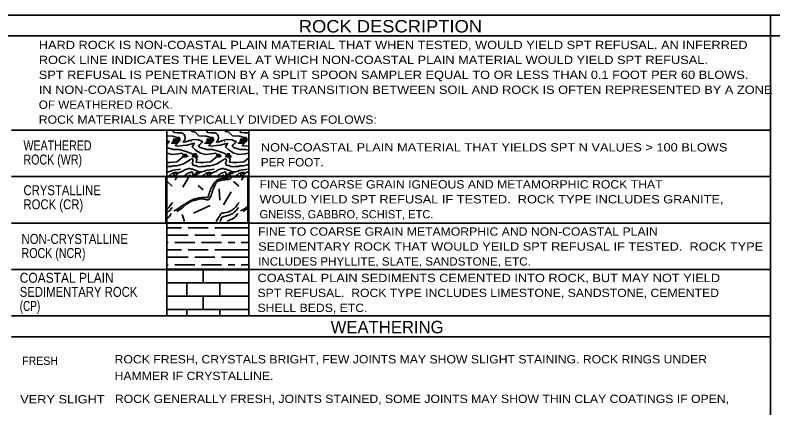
# Model space of a CAD drawing. Extents: x 2137492.6 to 2137529.1, y 2137475.8 to 2137563.
# Drawn here: x 2137510.82 to 2137519.94, y 2137553.49 to 2137558.22 of the extents above; entities that cross this region are included whole.
import ezdxf
from ezdxf.enums import TextEntityAlignment as Align

# ---------------------------------------------------------------- set-up
doc = ezdxf.new("R2010")
doc.units = 0
doc.header["$LTSCALE"] = 0.04
doc.layers.add('1', color=7, linetype='Continuous', lineweight=35)
doc.layers.add('2', color=7, linetype='Continuous')

msp = doc.modelspace()

# ---------------------------------------------------------------- linework, layer by layer
at = {"layer": '1'}
for p, q in [((2137493.171, 2137558.218), (2137528.371, 2137558.218)), ((2137519.912, 2137558.218), (2137519.912, 2137539.727)), ((2137493.171, 2137557.968), (2137528.371, 2137557.968)), ((2137519.912, 2137556.833), (2137510.771, 2137556.833)), ((2137512.642, 2137556.833), (2137512.642, 2137554.593)), ((2137512.642, 2137556.764), (2137512.708, 2137556.76)), ((2137513.63, 2137556.833), (2137513.63, 2137554.593)), ((2137512.693, 2137556.677), (2137512.772, 2137556.677)), ((2137512.709, 2137556.689), (2137512.779, 2137556.689)), ((2137512.716, 2137556.712), (2137512.797, 2137556.712)), ((2137512.797, 2137556.7), (2137512.716, 2137556.7)), ((2137512.798, 2137556.724), (2137512.719, 2137556.724)), ((2137512.884, 2137556.653), (2137512.929, 2137556.663)), ((2137513.096, 2137556.677), (2137513.174, 2137556.677)), ((2137513.111, 2137556.689), (2137513.182, 2137556.689)), ((2137513.119, 2137556.712), (2137513.2, 2137556.712)), ((2137513.2, 2137556.7), (2137513.119, 2137556.7)), ((2137513.2, 2137556.724), (2137513.122, 2137556.724)), ((2137513.287, 2137556.653), (2137513.331, 2137556.663)), ((2137513.498, 2137556.677), (2137513.576, 2137556.677)), ((2137513.514, 2137556.689), (2137513.584, 2137556.689)), ((2137513.521, 2137556.712), (2137513.602, 2137556.712)), ((2137513.602, 2137556.7), (2137513.521, 2137556.7)), ((2137513.603, 2137556.724), (2137513.524, 2137556.724)), ((2137512.884, 2137556.509), (2137512.835, 2137556.509)), ((2137512.841, 2137556.52), (2137512.9, 2137556.52)), ((2137512.88, 2137556.538), (2137512.847, 2137556.538)), ((2137512.888, 2137556.529), (2137512.848, 2137556.529)), ((2137512.927, 2137556.554), (2137512.906, 2137556.561)), ((2137512.951, 2137556.511), (2137513.02, 2137556.511)), ((2137513.003, 2137556.529), (2137512.963, 2137556.529)), ((2137512.963, 2137556.521), (2137513.013, 2137556.521)), ((2137512.964, 2137556.538), (2137512.998, 2137556.537)), ((2137512.965, 2137556.548), (2137512.999, 2137556.548)), ((2137513.287, 2137556.509), (2137513.238, 2137556.509)), ((2137513.244, 2137556.52), (2137513.302, 2137556.52)), ((2137513.283, 2137556.538), (2137513.249, 2137556.538)), ((2137513.291, 2137556.529), (2137513.25, 2137556.529)), ((2137513.33, 2137556.554), (2137513.308, 2137556.561)), ((2137513.353, 2137556.511), (2137513.423, 2137556.511)), ((2137513.405, 2137556.529), (2137513.365, 2137556.529)), ((2137513.365, 2137556.521), (2137513.416, 2137556.521)), ((2137513.367, 2137556.538), (2137513.4, 2137556.537)), ((2137513.368, 2137556.548), (2137513.401, 2137556.548)), ((2137513.629, 2137556.556), (2137513.63, 2137556.555)), ((2137512.642, 2137556.317), (2137512.643, 2137556.317)), ((2137512.74, 2137556.321), (2137512.772, 2137556.321)), ((2137512.74, 2137556.317), (2137512.768, 2137556.317)), ((2137512.74, 2137556.312), (2137512.764, 2137556.312)), ((2137512.74, 2137556.312), (2137512.76, 2137556.312)), ((2137512.951, 2137556.307), (2137512.954, 2137556.282)), ((2137513.011, 2137556.299), (2137512.964, 2137556.299)), ((2137512.979, 2137556.308), (2137513.033, 2137556.308)), ((2137512.991, 2137556.317), (2137513.046, 2137556.317)), ((2137513.143, 2137556.321), (2137513.175, 2137556.321)), ((2137513.143, 2137556.317), (2137513.171, 2137556.317)), ((2137513.143, 2137556.312), (2137513.167, 2137556.312)), ((2137513.143, 2137556.312), (2137513.163, 2137556.312)), ((2137513.354, 2137556.307), (2137513.357, 2137556.282)), ((2137513.413, 2137556.299), (2137513.367, 2137556.299)), ((2137513.381, 2137556.308), (2137513.435, 2137556.308)), ((2137513.393, 2137556.317), (2137513.448, 2137556.317)), ((2137513.545, 2137556.321), (2137513.577, 2137556.321)), ((2137513.545, 2137556.317), (2137513.573, 2137556.317)), ((2137513.545, 2137556.312), (2137513.569, 2137556.312)), ((2137513.545, 2137556.312), (2137513.565, 2137556.312)), ((2137519.912, 2137556.273), (2137510.771, 2137556.273)), ((2137512.646, 2137556.212), (2137512.709, 2137556.158)), ((2137512.765, 2137556.268), (2137512.742, 2137556.231)), ((2137512.908, 2137556.268), (2137512.836, 2137556.144)), ((2137513.446, 2137556.212), (2137513.509, 2137556.158)), ((2137513.565, 2137556.268), (2137513.542, 2137556.231)), ((2137513.02, 2137556.167), (2137513.082, 2137556.113)), ((2137513.272, 2137556.123), (2137513.281, 2137555.99)), ((2137513.416, 2137556.088), (2137513.325, 2137555.933)), ((2137512.963, 2137555.832), (2137513.166, 2137555.926)), ((2137513.618, 2137555.89), (2137513.562, 2137555.852)), ((2137512.827, 2137555.815), (2137512.854, 2137555.73)), ((2137519.912, 2137555.713), (2137510.771, 2137555.713)), ((2137512.641, 2137555.655), (2137512.661, 2137555.655)), ((2137512.661, 2137555.655), (2137512.821, 2137555.655)), ((2137512.901, 2137555.655), (2137513.141, 2137555.655)), ((2137513.221, 2137555.655), (2137513.461, 2137555.655)), ((2137513.461, 2137555.655), (2137513.621, 2137555.655)), ((2137512.641, 2137555.567), (2137512.661, 2137555.567)), ((2137512.661, 2137555.567), (2137512.901, 2137555.567)), ((2137512.981, 2137555.567), (2137513.221, 2137555.567)), ((2137513.301, 2137555.567), (2137513.461, 2137555.567)), ((2137513.461, 2137555.567), (2137513.629, 2137555.567)), ((2137512.641, 2137555.478), (2137512.66, 2137555.478)), ((2137512.74, 2137555.478), (2137512.98, 2137555.478)), ((2137513.06, 2137555.478), (2137513.3, 2137555.478)), ((2137513.38, 2137555.478), (2137513.46, 2137555.478)), ((2137513.54, 2137555.478), (2137513.629, 2137555.478)), ((2137512.641, 2137555.389), (2137512.661, 2137555.389)), ((2137512.661, 2137555.389), (2137512.821, 2137555.389)), ((2137512.901, 2137555.389), (2137513.141, 2137555.389)), ((2137513.221, 2137555.389), (2137513.461, 2137555.389)), ((2137513.461, 2137555.389), (2137513.621, 2137555.389)), ((2137512.641, 2137555.3), (2137512.661, 2137555.3)), ((2137512.661, 2137555.3), (2137512.901, 2137555.3)), ((2137512.981, 2137555.3), (2137513.221, 2137555.3)), ((2137513.301, 2137555.3), (2137513.461, 2137555.3)), ((2137513.461, 2137555.3), (2137513.629, 2137555.3)), ((2137512.641, 2137555.211), (2137512.66, 2137555.211)), ((2137512.74, 2137555.211), (2137512.98, 2137555.211)), ((2137513.06, 2137555.211), (2137513.3, 2137555.211)), ((2137513.38, 2137555.211), (2137513.46, 2137555.211)), ((2137513.54, 2137555.211), (2137513.629, 2137555.211)), ((2137519.912, 2137555.153), (2137510.771, 2137555.153)), ((2137513.082, 2137554.992), (2137513.082, 2137555.15)), ((2137512.642, 2137554.992), (2137513.63, 2137554.992)), ((2137512.882, 2137554.832), (2137512.882, 2137554.992)), ((2137513.282, 2137554.832), (2137513.282, 2137554.992)), ((2137512.642, 2137554.832), (2137513.63, 2137554.832)), ((2137513.082, 2137554.672), (2137513.082, 2137554.832)), ((2137512.642, 2137554.672), (2137513.63, 2137554.672)), ((2137512.882, 2137554.593), (2137512.882, 2137554.672)), ((2137513.282, 2137554.593), (2137513.282, 2137554.672)), ((2137519.912, 2137554.593), (2137510.771, 2137554.593)), ((2137519.912, 2137554.343), (2137510.771, 2137554.343))]:
    msp.add_line(p, q, dxfattribs=at)
for points in [[(2137512.642, 2137556.833), (2137513.63, 2137556.833), (2137513.63, 2137556.276), (2137512.642, 2137556.276)], [(2137512.63, 2137556.268), (2137513.618, 2137556.268), (2137513.618, 2137555.711), (2137512.63, 2137555.711)], [(2137512.641, 2137555.714), (2137513.629, 2137555.714), (2137513.629, 2137555.157), (2137512.641, 2137555.157)], [(2137512.642, 2137555.15), (2137513.63, 2137555.15), (2137513.63, 2137554.593), (2137512.642, 2137554.593)]]:
    msp.add_lwpolyline(points, close=True, dxfattribs=at)
for points in [[(2137512.682, 2137556.833), (2137512.708, 2137556.83), (2137512.732, 2137556.803), (2137512.768, 2137556.799), (2137512.782, 2137556.799)], [(2137512.708, 2137556.76), (2137512.716, 2137556.758), (2137512.764, 2137556.745), (2137512.792, 2137556.745), (2137512.8, 2137556.727), (2137512.8, 2137556.704), (2137512.76, 2137556.664), (2137512.744, 2137556.646), (2137512.776, 2137556.641), (2137512.836, 2137556.646), (2137512.884, 2137556.653)], [(2137512.782, 2137556.799), (2137512.802, 2137556.799), (2137512.819, 2137556.798), (2137512.838, 2137556.793), (2137512.852, 2137556.779), (2137512.858, 2137556.76), (2137512.862, 2137556.739), (2137512.859, 2137556.717), (2137512.838, 2137556.689), (2137512.871, 2137556.692), (2137512.927, 2137556.712)], [(2137512.909, 2137556.833), (2137512.908, 2137556.83), (2137512.919, 2137556.833)], [(2137512.942, 2137556.833), (2137512.945, 2137556.815), (2137512.986, 2137556.809), (2137513.03, 2137556.765), (2137513.11, 2137556.76)], [(2137513.085, 2137556.833), (2137513.111, 2137556.83), (2137513.135, 2137556.803), (2137513.171, 2137556.799), (2137513.185, 2137556.799)], [(2137513.11, 2137556.76), (2137513.119, 2137556.758), (2137513.167, 2137556.745), (2137513.195, 2137556.745), (2137513.203, 2137556.727), (2137513.203, 2137556.704), (2137513.163, 2137556.664), (2137513.147, 2137556.646), (2137513.179, 2137556.641), (2137513.239, 2137556.646), (2137513.287, 2137556.653)], [(2137513.185, 2137556.799), (2137513.205, 2137556.799), (2137513.221, 2137556.798), (2137513.24, 2137556.793), (2137513.255, 2137556.779), (2137513.26, 2137556.76), (2137513.265, 2137556.739), (2137513.261, 2137556.717), (2137513.24, 2137556.689), (2137513.273, 2137556.692), (2137513.33, 2137556.712)], [(2137513.312, 2137556.833), (2137513.311, 2137556.83), (2137513.322, 2137556.833)], [(2137513.345, 2137556.833), (2137513.348, 2137556.815), (2137513.389, 2137556.809), (2137513.433, 2137556.765), (2137513.513, 2137556.76)], [(2137513.487, 2137556.833), (2137513.513, 2137556.83), (2137513.537, 2137556.803), (2137513.573, 2137556.799), (2137513.587, 2137556.799)], [(2137513.513, 2137556.76), (2137513.521, 2137556.758), (2137513.569, 2137556.745), (2137513.597, 2137556.745), (2137513.605, 2137556.727), (2137513.605, 2137556.704), (2137513.565, 2137556.664), (2137513.549, 2137556.646), (2137513.581, 2137556.641), (2137513.63, 2137556.645)], [(2137513.587, 2137556.799), (2137513.607, 2137556.799), (2137513.624, 2137556.798), (2137513.63, 2137556.796)], [(2137512.642, 2137556.708), (2137512.65, 2137556.705), (2137512.671, 2137556.697), (2137512.659, 2137556.679), (2137512.642, 2137556.661)], [(2137512.93, 2137556.712), (2137512.963, 2137556.719), (2137513.025, 2137556.715), (2137513.053, 2137556.705), (2137513.073, 2137556.697), (2137513.062, 2137556.679), (2137513.042, 2137556.659), (2137513.026, 2137556.641), (2137513.043, 2137556.623), (2137513.121, 2137556.599), (2137513.191, 2137556.599), (2137513.276, 2137556.575), (2137513.308, 2137556.561)], [(2137512.931, 2137556.695), (2137512.935, 2137556.695), (2137512.931, 2137556.695)], [(2137512.931, 2137556.663), (2137512.956, 2137556.672), (2137512.973, 2137556.674), (2137512.963, 2137556.657), (2137512.948, 2137556.63), (2137512.99, 2137556.59), (2137513.047, 2137556.553), (2137513.111, 2137556.538), (2137513.181, 2137556.545), (2137513.227, 2137556.556)], [(2137513.332, 2137556.712), (2137513.365, 2137556.719), (2137513.428, 2137556.715), (2137513.455, 2137556.705), (2137513.476, 2137556.697), (2137513.464, 2137556.679), (2137513.445, 2137556.659), (2137513.429, 2137556.641), (2137513.446, 2137556.623), (2137513.524, 2137556.599), (2137513.593, 2137556.599), (2137513.63, 2137556.589)], [(2137513.333, 2137556.695), (2137513.337, 2137556.695), (2137513.333, 2137556.695)], [(2137513.334, 2137556.663), (2137513.358, 2137556.672), (2137513.375, 2137556.674), (2137513.365, 2137556.657), (2137513.351, 2137556.63), (2137513.393, 2137556.59), (2137513.449, 2137556.553), (2137513.513, 2137556.538), (2137513.584, 2137556.545), (2137513.629, 2137556.556)], [(2137512.642, 2137556.623), (2137512.719, 2137556.599), (2137512.789, 2137556.599), (2137512.874, 2137556.575), (2137512.906, 2137556.561)], [(2137512.824, 2137556.556), (2137512.832, 2137556.547), (2137512.848, 2137556.533), (2137512.828, 2137556.501), (2137512.8, 2137556.479), (2137512.764, 2137556.452), (2137512.724, 2137556.447), (2137512.68, 2137556.443), (2137512.642, 2137556.443)], [(2137512.642, 2137556.555), (2137512.645, 2137556.553), (2137512.708, 2137556.538), (2137512.779, 2137556.545), (2137512.824, 2137556.556)], [(2137512.852, 2137556.429), (2137512.884, 2137556.452), (2137512.927, 2137556.478)], [(2137512.93, 2137556.554), (2137512.939, 2137556.552), (2137512.945, 2137556.55), (2137512.952, 2137556.543), (2137512.954, 2137556.53), (2137512.951, 2137556.511)], [(2137512.95, 2137556.442), (2137512.954, 2137556.453), (2137512.957, 2137556.467), (2137512.958, 2137556.48), (2137512.953, 2137556.485), (2137512.94, 2137556.485), (2137512.93, 2137556.478)], [(2137513.227, 2137556.556), (2137513.235, 2137556.547), (2137513.251, 2137556.533), (2137513.231, 2137556.501), (2137513.203, 2137556.479), (2137513.167, 2137556.452), (2137513.127, 2137556.447), (2137513.083, 2137556.443), (2137513.035, 2137556.443), (2137512.995, 2137556.447), (2137513.003, 2137556.483), (2137512.987, 2137556.506), (2137512.951, 2137556.511)], [(2137513.255, 2137556.429), (2137513.287, 2137556.452), (2137513.33, 2137556.478)], [(2137513.332, 2137556.554), (2137513.341, 2137556.552), (2137513.347, 2137556.55), (2137513.355, 2137556.543), (2137513.357, 2137556.53), (2137513.353, 2137556.511)], [(2137513.353, 2137556.442), (2137513.357, 2137556.453), (2137513.36, 2137556.467), (2137513.36, 2137556.48), (2137513.355, 2137556.485), (2137513.342, 2137556.485), (2137513.332, 2137556.478)], [(2137513.63, 2137556.499), (2137513.605, 2137556.479), (2137513.569, 2137556.452), (2137513.529, 2137556.447), (2137513.485, 2137556.443), (2137513.437, 2137556.443), (2137513.397, 2137556.447), (2137513.405, 2137556.483), (2137513.389, 2137556.506), (2137513.353, 2137556.511)], [(2137512.852, 2137556.429), (2137512.82, 2137556.42), (2137512.792, 2137556.411), (2137512.76, 2137556.402), (2137512.716, 2137556.402), (2137512.7, 2137556.393), (2137512.672, 2137556.393), (2137512.656, 2137556.393), (2137512.642, 2137556.391)], [(2137513.255, 2137556.429), (2137513.223, 2137556.42), (2137513.195, 2137556.411), (2137513.163, 2137556.402), (2137513.119, 2137556.402), (2137513.103, 2137556.393), (2137513.075, 2137556.393), (2137513.059, 2137556.393), (2137513.035, 2137556.389), (2137513.011, 2137556.393), (2137512.991, 2137556.407), (2137512.971, 2137556.407), (2137512.959, 2137556.411), (2137512.947, 2137556.429), (2137512.95, 2137556.442)], [(2137513.63, 2137556.421), (2137513.625, 2137556.42), (2137513.597, 2137556.411), (2137513.565, 2137556.402), (2137513.521, 2137556.402), (2137513.505, 2137556.393), (2137513.477, 2137556.393), (2137513.461, 2137556.393), (2137513.437, 2137556.389), (2137513.413, 2137556.393), (2137513.393, 2137556.407), (2137513.373, 2137556.407), (2137513.361, 2137556.411), (2137513.349, 2137556.429), (2137513.353, 2137556.442)], [(2137512.808, 2137556.362), (2137512.784, 2137556.357), (2137512.752, 2137556.353), (2137512.728, 2137556.348), (2137512.708, 2137556.344), (2137512.692, 2137556.339), (2137512.664, 2137556.33), (2137512.642, 2137556.33)], [(2137512.67, 2137556.282), (2137512.688, 2137556.294), (2137512.704, 2137556.308), (2137512.728, 2137556.317), (2137512.74, 2137556.321), (2137512.736, 2137556.308), (2137512.724, 2137556.29), (2137512.717, 2137556.282)], [(2137512.788, 2137556.317), (2137512.776, 2137556.308), (2137512.76, 2137556.299), (2137512.748, 2137556.285), (2137512.742, 2137556.282)], [(2137512.788, 2137556.317), (2137512.792, 2137556.321), (2137512.828, 2137556.335)], [(2137512.828, 2137556.335), (2137512.847, 2137556.344), (2137512.861, 2137556.354), (2137512.883, 2137556.363), (2137512.907, 2137556.37), (2137512.92, 2137556.369), (2137512.929, 2137556.364)], [(2137512.927, 2137556.322), (2137512.924, 2137556.321), (2137512.9, 2137556.312), (2137512.876, 2137556.299), (2137512.864, 2137556.29), (2137512.854, 2137556.282)], [(2137512.907, 2137556.283), (2137512.914, 2137556.287), (2137512.922, 2137556.29), (2137512.928, 2137556.287)], [(2137512.97, 2137556.354), (2137512.963, 2137556.356), (2137512.951, 2137556.36), (2137512.94, 2137556.363), (2137512.931, 2137556.364)], [(2137512.951, 2137556.307), (2137512.95, 2137556.317), (2137512.947, 2137556.329), (2137512.942, 2137556.329), (2137512.935, 2137556.325), (2137512.931, 2137556.322)], [(2137513.211, 2137556.362), (2137513.187, 2137556.357), (2137513.155, 2137556.353), (2137513.131, 2137556.348), (2137513.111, 2137556.344), (2137513.095, 2137556.339), (2137513.067, 2137556.33), (2137513.027, 2137556.33), (2137512.995, 2137556.344), (2137512.975, 2137556.353), (2137512.97, 2137556.354)], [(2137513.072, 2137556.282), (2137513.091, 2137556.294), (2137513.107, 2137556.308), (2137513.131, 2137556.317), (2137513.143, 2137556.321), (2137513.139, 2137556.308), (2137513.127, 2137556.29), (2137513.12, 2137556.282)], [(2137513.191, 2137556.317), (2137513.179, 2137556.308), (2137513.163, 2137556.299), (2137513.151, 2137556.285), (2137513.145, 2137556.282)], [(2137513.191, 2137556.317), (2137513.195, 2137556.321), (2137513.231, 2137556.335)], [(2137513.231, 2137556.335), (2137513.249, 2137556.344), (2137513.263, 2137556.354), (2137513.285, 2137556.363), (2137513.309, 2137556.37), (2137513.323, 2137556.369), (2137513.331, 2137556.364)], [(2137513.33, 2137556.322), (2137513.327, 2137556.321), (2137513.303, 2137556.312), (2137513.279, 2137556.299), (2137513.267, 2137556.29), (2137513.256, 2137556.282)], [(2137513.309, 2137556.283), (2137513.316, 2137556.287), (2137513.324, 2137556.29), (2137513.331, 2137556.287)], [(2137513.372, 2137556.354), (2137513.365, 2137556.356), (2137513.353, 2137556.36), (2137513.342, 2137556.363), (2137513.334, 2137556.364)], [(2137513.354, 2137556.307), (2137513.352, 2137556.317), (2137513.349, 2137556.329), (2137513.345, 2137556.329), (2137513.337, 2137556.325), (2137513.334, 2137556.322)], [(2137513.613, 2137556.362), (2137513.589, 2137556.357), (2137513.557, 2137556.353), (2137513.533, 2137556.348), (2137513.513, 2137556.344), (2137513.497, 2137556.339), (2137513.469, 2137556.33), (2137513.429, 2137556.33), (2137513.397, 2137556.344), (2137513.377, 2137556.353), (2137513.372, 2137556.354)], [(2137513.475, 2137556.282), (2137513.493, 2137556.294), (2137513.509, 2137556.308), (2137513.533, 2137556.317), (2137513.545, 2137556.321), (2137513.541, 2137556.308), (2137513.529, 2137556.29), (2137513.522, 2137556.282)], [(2137513.593, 2137556.317), (2137513.581, 2137556.308), (2137513.565, 2137556.299), (2137513.553, 2137556.285), (2137513.547, 2137556.282)], [(2137513.593, 2137556.317), (2137513.597, 2137556.321), (2137513.63, 2137556.334)]]:
    msp.add_lwpolyline(points, dxfattribs=at)
for points in [[(2137513.146, 2137556.05), (2137513.147, 2137556.052), (2137513.158, 2137556.085), (2137513.186, 2137556.148), (2137513.216, 2137556.2), (2137513.25, 2137556.231), (2137513.294, 2137556.245), (2137513.35, 2137556.253), (2137513.376, 2137556.258), (2137513.395, 2137556.268)], [(2137513.424, 2137556.268), (2137513.403, 2137556.24), (2137513.366, 2137556.236), (2137513.299, 2137556.226), (2137513.254, 2137556.215), (2137513.221, 2137556.165), (2137513.2, 2137556.119), (2137513.187, 2137556.08), (2137513.176, 2137556.05)], [(2137512.728, 2137555.858), (2137512.808, 2137555.906), (2137512.858, 2137555.94), (2137512.912, 2137555.972), (2137512.965, 2137556), (2137513.03, 2137556.016), (2137513.09, 2137556.021), (2137513.118, 2137556.021), (2137513.138, 2137556.026), (2137513.146, 2137556.05)], [(2137513.176, 2137556.05), (2137513.176, 2137556.045), (2137513.166, 2137556.023), (2137513.149, 2137555.997), (2137513.09, 2137556.002), (2137513.027, 2137556), (2137512.973, 2137555.986), (2137512.91, 2137555.962), (2137512.838, 2137555.904), (2137512.762, 2137555.852)], [(2137512.63, 2137555.867), (2137512.653, 2137555.888), (2137512.712, 2137555.962)], [(2137513.285, 2137555.808), (2137513.298, 2137555.826), (2137513.338, 2137555.837), (2137513.406, 2137555.855), (2137513.453, 2137555.888), (2137513.512, 2137555.962)], [(2137512.63, 2137555.823), (2137512.654, 2137555.842), (2137512.706, 2137555.898)], [(2137513.307, 2137555.783), (2137513.362, 2137555.799), (2137513.419, 2137555.818), (2137513.454, 2137555.842), (2137513.506, 2137555.898)], [(2137513.528, 2137555.858), (2137513.608, 2137555.906), (2137513.618, 2137555.913)], [(2137512.63, 2137555.763), (2137512.658, 2137555.778), (2137512.696, 2137555.826)], [(2137513.235, 2137555.73), (2137513.264, 2137555.775), (2137513.285, 2137555.808)], [(2137513.307, 2137555.783), (2137513.288, 2137555.743), (2137513.282, 2137555.73)], [(2137513.369, 2137555.73), (2137513.39, 2137555.744), (2137513.458, 2137555.778), (2137513.496, 2137555.826)]]:
    msp.add_spline(points, degree=3, dxfattribs=at)

# ---------------------------------------------------------------- texts
at = {"layer": '1', "width": 1.1}
msp.add_text('ROCK DESCRIPTION', height=0.15, dxfattribs=at).set_placement((2137515.3355, 2137558.009), align=Align.CENTER)
at = {"layer": '1'}
for s, height, width, p in [('HARD ROCK IS NON-COASTAL PLAIN MATERIAL THAT WHEN TESTED, WOULD YIELD SPT REFUSAL. AN INFERRED ', 0.1, 1.15, (2137511.101, 2137557.809)), ('ROCK LINE INDICATES THE LEVEL AT WHICH NON-COASTAL PLAIN MATERIAL WOULD YIELD SPT REFUSAL.  ', 0.1, 1.15, (2137511.101, 2137557.629)), ('SPT REFUSAL IS PENETRATION BY A SPLIT SPOON SAMPLER EQUAL TO OR LESS THAN 0.1 FOOT PER 60 BLOWS.  ', 0.1, 1.15, (2137511.101, 2137557.449)), ('IN NON-COASTAL PLAIN MATERIAL, THE TRANSITION BETWEEN SOIL AND ROCK IS OFTEN REPRESENTED BY A ZONE ', 0.1, 1.15, (2137511.101, 2137557.269)), ('OF WEATHERED ROCK.  ', 0.1, 1.05, (2137511.101, 2137557.089)), ('ROCK MATERIALS ARE TYPICALLY DIVIDED AS FOLOWS:', 0.1, 1.1, (2137511.101, 2137556.909)), ('WEATHERED', 0.12, 0.8, (2137510.916, 2137556.588)), ('NON-COASTAL PLAIN MATERIAL THAT YIELDS SPT N VALUES > 100 BLOWS ', 0.1, 1.15, (2137513.775, 2137556.575)), ('ROCK (WR)', 0.12, 0.8, (2137510.916, 2137556.418)), ('PER FOOT.', 0.1, 1.05, (2137513.775, 2137556.395)), ('FINE TO COARSE GRAIN IGNEOUS AND METAMORPHIC ROCK THAT ', 0.1, 1.1, (2137513.759, 2137556.129)), ('CRYSTALLINE', 0.12, 0.85, (2137510.916, 2137556.048)), ('WOULD YIELD SPT REFUSAL IF TESTED.  ROCK TYPE INCLUDES GRANITE, ', 0.1, 1.15, (2137513.759, 2137555.949)), ('ROCK (CR)', 0.12, 0.85, (2137510.916, 2137555.878)), ('FINE TO COARSE GRAIN METAMORPHIC AND NON-COASTAL PLAIN ', 0.1, 1.1, (2137513.742, 2137555.56)), ('NON-CRYSTALLINE', 0.12, 0.85, (2137510.893, 2137555.461)), ('SEDIMENTARY ROCK THAT WOULD YEILD SPT REFUSAL IF TESTED.  ROCK TYPE ', 0.1, 1.15, (2137513.742, 2137555.38)), ('ROCK (NCR)', 0.12, 0.8, (2137510.893, 2137555.291)), ('INCLUDES PHYLLITE, SLATE, SANDSTONE, ETC.', 0.1, 1.05, (2137513.742, 2137555.2)), ('COASTAL PLAIN', 0.12, 0.9, (2137510.871, 2137554.993)), ('COASTAL PLAIN SEDIMENTS CEMENTED INTO ROCK, BUT MAY NOT YIELD ', 0.1, 1.15, (2137513.735, 2137555.001)), ('SEDIMENTARY ROCK', 0.12, 0.85, (2137510.871, 2137554.823)), ('SPT REFUSAL.  ROCK TYPE INCLUDES LIMESTONE, SANDSTONE, CEMENTED ', 0.1, 1.1, (2137513.735, 2137554.821)), ('(CP)', 0.12, 0.75, (2137510.871, 2137554.653)), ('SHELL BEDS, ETC.', 0.1, 1.1, (2137513.735, 2137554.641))]:
    msp.add_text(s, height=height, dxfattribs=dict(at, width=width)).set_placement(p)
for s, height, p in [('GNEISS, GABBRO, SCHIST, ETC.', 0.1, (2137513.759, 2137555.769)), ('WEATHERING', 0.15, (2137514.616, 2137554.384))]:
    msp.add_text(s, height=height, dxfattribs=at).set_placement(p)
at = {"layer": '2'}
for s, width, p in [('FRESH', 0.95, (2137510.901, 2137554.003)), ('ROCK FRESH, CRYSTALS BRIGHT, FEW JOINTS MAY SHOW SLIGHT STAINING. ROCK RINGS UNDER ', 1.1, (2137512.014, 2137554.021)), ('HAMMER IF CRYSTALLINE.', 1.1, (2137512.014, 2137553.821)), ('ROCK GENERALLY FRESH, JOINTS STAINED, SOME JOINTS MAY SHOW THIN CLAY COATINGS IF OPEN, ', 1.1, (2137512.017, 2137553.544)), ('VERY SLIGHT ', 1.15, (2137510.877, 2137553.539))]:
    msp.add_text(s, height=0.1, dxfattribs=dict(at, width=width)).set_placement(p)

doc.saveas('drawing.dxf')
